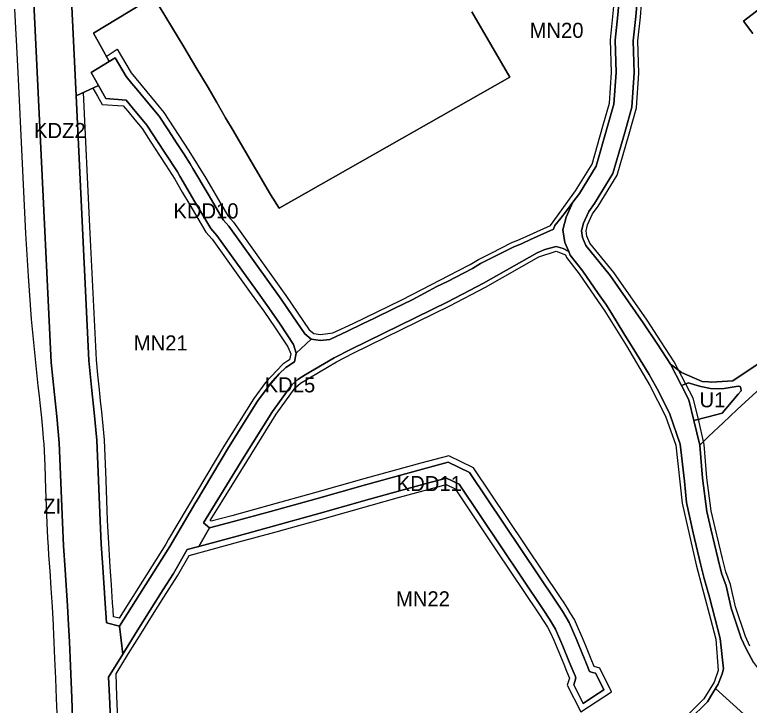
# Model space of a CAD drawing. Extents: x 7440055 to 7442242, y 5549003 to 5552256.
# Drawn here: x 7440527.7 to 7441014, y 5550680.3 to 5551137.8 of the extents above; entities that cross this region are included whole.
import ezdxf

# ---------------------------------------------------------------- set-up
doc = ezdxf.new("R2010")
doc.units = 0
for name, color, linetype in [('linie_rozgraniczajace', 7, 'Continuous'), ('linie_zabudowy_nieprzekraczalne', 7, 'Continuous'), ('oznaczenia_przeznaczen', 7, 'Continuous')]:
    doc.layers.add(name, color=color, linetype=linetype)

msp = doc.modelspace()

# ---------------------------------------------------------------- linework, layer by layer
at = {"layer": 'linie_rozgraniczajace'}
for points in [[(7440830.37, 5551139.67), (7440855.55, 5551096.35), (7440702.84, 5551009.63), (7440697, 5551018.73), (7440687.09, 5551035.67), (7440677.19, 5551052.65), (7440672.26, 5551061.09), (7440667.34, 5551069.53), (7440661.49, 5551079.54), (7440655.65, 5551089.56), (7440647.67, 5551103.05), (7440639.69, 5551116.53), (7440619.62, 5551149.85), (7440579.81, 5551125.56), (7440585.04, 5551116.14), (7440590.25, 5551106.84), (7440578.25, 5551099.45), (7440583.15, 5551090.81), (7440568.31, 5551084.03), (7440561.3, 5551229.74)], [(7440561.3, 5551229.74), (7440568.31, 5551084.03), (7440576.75, 5550908.58), (7440578.8, 5550888.77), (7440580.36, 5550874.18), (7440582.12, 5550855.83), (7440584.21, 5550802.55), (7440584.95, 5550787.34), (7440585.97, 5550771.61), (7440587.51, 5550747.86), (7440588.35, 5550734.83), (7440597.06, 5550732.72), (7440599.32, 5550714.25), (7440589.84, 5550698.98), (7440590.37, 5550686.14), (7440591.21, 5550666.06)], [(7440573.92, 5550172.69), (7440582.76, 5550197.27), (7440579.13, 5550273.35), (7440576.06, 5550392.67), (7440574.03, 5550461.9), (7440571.71, 5550531.98), (7440566.39, 5550642.67), (7440566.17, 5550647.16), (7440566.21, 5550665.57), (7440565.4, 5550685.1), (7440564.29, 5550711.77), (7440563.86, 5550722.35), (7440563.39, 5550733.5), (7440562.57, 5550746.25), (7440561.03, 5550769.99), (7440559.99, 5550785.92), (7440559.23, 5550801.45), (7440557.17, 5550854.15), (7440555.49, 5550871.65), (7440553.94, 5550886.18), (7440551.79, 5550907.38), (7440536.34, 5551228.21)], [(7440536.34, 5551228.21), (7440551.79, 5550907.38), (7440553.94, 5550886.18), (7440555.49, 5550871.65), (7440557.17, 5550854.15), (7440559.23, 5550801.45), (7440559.99, 5550785.92), (7440561.03, 5550769.99), (7440562.57, 5550746.25), (7440563.39, 5550733.5), (7440563.86, 5550722.35), (7440564.29, 5550711.77), (7440565.4, 5550685.1), (7440566.21, 5550665.57)], [(7440928.54, 5551156.26), (7440927.02, 5551137.61), (7440925.17, 5551120.94), (7440925.87, 5551099.38), (7440924.41, 5551078.59), (7440919.98, 5551063.06), (7440912.67, 5551037.44), (7440907.11, 5551028.4), (7440901.55, 5551019.35), (7440897.25, 5551013.55), (7440892.96, 5551007.75), (7440889.14, 5551002.96), (7440885.33, 5550998.16), (7440884.33, 5550995.64), (7440869.26, 5550988.88), (7440863.61, 5550986.23), (7440857.59, 5550983.83), (7440844.91, 5550977.34), (7440836.17, 5550972.94), (7440830.69, 5550969.6), (7440814.23, 5550961.11), (7440807.18, 5550957.61), (7440790.76, 5550948.96), (7440778.97, 5550943.15), (7440765.8, 5550936.74), (7440757.96, 5550932.92), (7440748, 5550928.18), (7440736.35, 5550922.68), (7440730.09, 5550921.98), (7440724.04, 5550922.85), (7440719.69, 5550926.27), (7440711.67, 5550938.27), (7440704, 5550949.42), (7440669.33, 5550997.74), (7440665.67, 5551001.91), (7440655.65, 5551018.94), (7440645.7, 5551035.85), (7440643.93, 5551038.87), (7440639.59, 5551045.54), (7440635.24, 5551052.2), (7440629.25, 5551061.39), (7440623.26, 5551070.58), (7440613.2, 5551082.79), (7440609.12, 5551087.6), (7440605.28, 5551092.25), (7440601.45, 5551096.91), (7440594.17, 5551109.25), (7440590.25, 5551106.84), (7440585.04, 5551116.14), (7440579.81, 5551125.56), (7440619.62, 5551149.85), (7440639.69, 5551116.53), (7440647.67, 5551103.05), (7440655.65, 5551089.56), (7440661.49, 5551079.54), (7440667.34, 5551069.53), (7440672.26, 5551061.09), (7440677.19, 5551052.65), (7440687.09, 5551035.67), (7440697, 5551018.73), (7440702.84, 5551009.63), (7440855.55, 5551096.35), (7440830.37, 5551139.67)], [(7441010.3, 5550674.43), (7440991.64, 5550691.44), (7440993.4, 5550694.37), (7440996.09, 5550701.19), (7440996.9, 5550704.49), (7440994.79, 5550724.62), (7440991.22, 5550738.27), (7440987.64, 5550751.91), (7440984.21, 5550764.34), (7440981.75, 5550773.95), (7440976.83, 5550794.47), (7440972.47, 5550814.57), (7440971.17, 5550828.79), (7440968.31, 5550853.23), (7440961.35, 5550873.06), (7440954.1, 5550887.88), (7440947.66, 5550899.42), (7440939.34, 5550913.21), (7440931.03, 5550926.58), (7440922.71, 5550939.96), (7440918.97, 5550945.95), (7440914.05, 5550953.02), (7440903.74, 5550967.82), (7440895.53, 5550978.55), (7440894.5, 5550980.96), (7440891.98, 5550986.84), (7440890.64, 5550995.24), (7440892.81, 5551003.56), (7440897.25, 5551013.55), (7440901.55, 5551019.35), (7440907.11, 5551028.4), (7440912.67, 5551037.44), (7440919.98, 5551063.06), (7440924.41, 5551078.59), (7440925.87, 5551099.38), (7440925.17, 5551120.94), (7440927.02, 5551137.61), (7440928.54, 5551156.26)], [(7440940.44, 5551154.55), (7440938.97, 5551136.46), (7440937.19, 5551120.47), (7440937.88, 5551099.15), (7440936.29, 5551076.5), (7440931.52, 5551059.77), (7440923.75, 5551032.57), (7440911.5, 5551012.62), (7440907.68, 5551007.46), (7440904.17, 5550999.58), (7440902.88, 5550994.65), (7440903.59, 5550990.2), (7440905.9, 5550984.81), (7440921.91, 5550965.1), (7440943.85, 5550933.7), (7440953.2, 5550919.47), (7440961.8, 5550906.31), (7440969.13, 5550892.18), (7440974.08, 5550882.66), (7440977.41, 5550869.05), (7440981.27, 5550852.56), (7440983.02, 5550830.68), (7440985.92, 5550808.58)], [(7440902.88, 5550994.65), (7440904.17, 5550999.58), (7440907.68, 5551007.46), (7440911.5, 5551012.62), (7440923.75, 5551032.57), (7440931.52, 5551059.77), (7440936.29, 5551076.5), (7440937.88, 5551099.15), (7440937.19, 5551120.47), (7440938.97, 5551136.46), (7440940.44, 5551154.55)], [(7441016.3, 5551125.31), (7441010.11, 5551133.47), (7441029.47, 5551148.49)], [(7441029.47, 5551148.49), (7441010.11, 5551133.47), (7441016.3, 5551125.31)], [(7440555.81, 5550675.03), (7440555.41, 5550684.69), (7440554.86, 5550698.02), (7440554.3, 5550711.36), (7440553.86, 5550721.94), (7440553.43, 5550732.51), (7440553.38, 5550733.43), (7440552.59, 5550745.61), (7440551.8, 5550757.78), (7440551.05, 5550769.34), (7440550.37, 5550779.81), (7440550.01, 5550785.35), (7440549.65, 5550790.89), (7440549.25, 5550801.01), (7440548.81, 5550812.22), (7440548.37, 5550823.42), (7440547.75, 5550839.07), (7440547.19, 5550853.48), (7440546.83, 5550857.06), (7440546.47, 5550860.64), (7440545.54, 5550870.64), (7440544.62, 5550880.64), (7440543.99, 5550885.14), (7440543.31, 5550891.84), (7440541.07, 5550913.93), (7440538.83, 5550936.02), (7440536.88, 5550964.45), (7440534.93, 5550992.87), (7440532.5, 5551043.93), (7440530.08, 5551094.99), (7440528.85, 5551120.92), (7440528.68, 5551124.58), (7440527.66, 5551141.39)], [(7441019.97, 5550906.59), (7441003.04, 5550895.28), (7440996.05, 5550894.8), (7440989.07, 5550894.32), (7440987.06, 5550894.5), (7440982.84, 5550894.87), (7440969.2, 5550900.82), (7440961.8, 5550906.31), (7440953.2, 5550919.47), (7440943.85, 5550933.7), (7440921.91, 5550965.1), (7440905.9, 5550984.81), (7440903.59, 5550990.2), (7440902.88, 5550994.65)], [(7440591.21, 5550666.06), (7440590.37, 5550686.14), (7440589.84, 5550698.98), (7440599.32, 5550714.25), (7440608.81, 5550729.52), (7440625.92, 5550757.04), (7440632.83, 5550767.67), (7440641.9, 5550783.4), (7440649.65, 5550785.5), (7440675.05, 5550792.36), (7440699.6, 5550799.09), (7440729.93, 5550807.47), (7440762.62, 5550816.79), (7440800.16, 5550827.16), (7440813.64, 5550830.69), (7440821.9, 5550826.7), (7440877.53, 5550743.73), (7440881.85, 5550737.27), (7440885.74, 5550730.65), (7440890.63, 5550719.56), (7440894.87, 5550709.12), (7440896.77, 5550704.44), (7440898.67, 5550699.76), (7440899.23, 5550698.4), (7440898.54, 5550696.11), (7440897.85, 5550693.83), (7440900.9, 5550687.7), (7440903.95, 5550681.57), (7440910.87, 5550686.02), (7440917.79, 5550690.46), (7440914.99, 5550696), (7440912.2, 5550701.53), (7440910.23, 5550702.11), (7440908.26, 5550702.7), (7440906.23, 5550707.71), (7440904.21, 5550712.71), (7440903.62, 5550714.16), (7440899.84, 5550723.46), (7440894.66, 5550735.22), (7440890.33, 5550742.58), (7440885.83, 5550749.3), (7440828.69, 5550834.53), (7440814.66, 5550841.29), (7440797.56, 5550836.81), (7440759.92, 5550826.42), (7440727.23, 5550817.1), (7440696.95, 5550808.73), (7440672.43, 5550802.01), (7440656.69, 5550797.76), (7440652.64, 5550801.17), (7440679.44, 5550844.71), (7440698.34, 5550874.88), (7440711.19, 5550892.59), (7440715.1, 5550896.18), (7440720.07, 5550899.24), (7440739.24, 5550910.39), (7440750.46, 5550916.27), (7440814.49, 5550947.54), (7440838.02, 5550959.86), (7440873.51, 5550980.06), (7440878.68, 5550982.11), (7440886.17, 5550984.24), (7440890.77, 5550982.84), (7440894.5, 5550980.96), (7440895.53, 5550978.55), (7440903.74, 5550967.82), (7440914.05, 5550953.02), (7440918.97, 5550945.95), (7440922.71, 5550939.96), (7440931.03, 5550926.58), (7440939.34, 5550913.21), (7440947.66, 5550899.42), (7440954.1, 5550887.88), (7440961.35, 5550873.06), (7440968.31, 5550853.23), (7440971.17, 5550828.79), (7440972.47, 5550814.57), (7440976.83, 5550794.47), (7440981.75, 5550773.95), (7440984.21, 5550764.34), (7440987.64, 5550751.91), (7440991.22, 5550738.27), (7440994.79, 5550724.62), (7440996.9, 5550704.49), (7440996.09, 5550701.19), (7440993.4, 5550694.37), (7440991.64, 5550691.44), (7440989.88, 5550688.5), (7440986.37, 5550682.63), (7440974.26, 5550670.64)], [(7441021.65, 5550890.55), (7441006.03, 5550876.25), (7440996.62, 5550867.42), (7440987.21, 5550858.58), (7440981.27, 5550852.56), (7440977.41, 5550869.05), (7440986.76, 5550871.41), (7440996.12, 5550873.77), (7441006.72, 5550886.42), (7441008.56, 5550888.6), (7441008.46, 5550890.36), (7441007.92, 5550891.37), (7441006.86, 5550891.79), (7441005.24, 5550891.51), (7440997.43, 5550890.16), (7440993.69, 5550889.97), (7440988.24, 5550890.24), (7440981.89, 5550891.42), (7440977.88, 5550892.66), (7440973.88, 5550893.9), (7440969.13, 5550892.18), (7440961.8, 5550906.31), (7440969.2, 5550900.82), (7440982.84, 5550894.87), (7440987.06, 5550894.5), (7440989.07, 5550894.32), (7440996.05, 5550894.8), (7441003.04, 5550895.28), (7441019.97, 5550906.59)], [(7441016.81, 5550708.73), (7441011.75, 5550718.07), (7441008.62, 5550724.81), (7441002.01, 5550744.64), (7440998.67, 5550759.48), (7440995.7, 5550767.84), (7440993.4, 5550776.83), (7440988.51, 5550797.2), (7440985.92, 5550808.58), (7440983.02, 5550830.68), (7440981.27, 5550852.56), (7440987.21, 5550858.58), (7440996.62, 5550867.42), (7441006.03, 5550876.25), (7441021.65, 5550890.55)], [(7440985.92, 5550808.58), (7440988.51, 5550797.2), (7440993.4, 5550776.83), (7440995.7, 5550767.84), (7440998.67, 5550759.48), (7441002.01, 5550744.64), (7441008.62, 5550724.81), (7441011.75, 5550718.07), (7441016.81, 5550708.73), (7441021.5, 5550702.43), (7441027.75, 5550694.5), (7441043.14, 5550686.11), (7441057.84, 5550678.1)], [(7440974.26, 5550670.64), (7440986.37, 5550682.63), (7440989.88, 5550688.5), (7440991.64, 5550691.44), (7441010.3, 5550674.43)]]:
    msp.add_lwpolyline(points, dxfattribs=at)
for points in [[(7440578.25, 5551099.45), (7440590.25, 5551106.84), (7440594.17, 5551109.25), (7440601.45, 5551096.91), (7440605.28, 5551092.25), (7440609.12, 5551087.6), (7440613.2, 5551082.79), (7440623.26, 5551070.58), (7440629.25, 5551061.39), (7440635.24, 5551052.2), (7440639.59, 5551045.54), (7440643.93, 5551038.87), (7440645.7, 5551035.85), (7440655.65, 5551018.94), (7440665.67, 5551001.91), (7440669.33, 5550997.74), (7440704, 5550949.42), (7440711.67, 5550938.27), (7440719.69, 5550926.27), (7440724.04, 5550922.85), (7440714.02, 5550913.56), (7440712.26, 5550919.39), (7440703.4, 5550932.66), (7440695.82, 5550943.66), (7440687.68, 5550955.01), (7440661.49, 5550991.51), (7440657.53, 5550996.03), (7440647.03, 5551013.87), (7440637.08, 5551030.78), (7440635.43, 5551033.6), (7440626.87, 5551046.75), (7440615.19, 5551064.65), (7440605.53, 5551076.38), (7440601.45, 5551081.19), (7440588.04, 5551082.17), (7440583.15, 5551090.81)], [(7440568.31, 5551084.03), (7440583.15, 5551090.81), (7440588.04, 5551082.17), (7440601.45, 5551081.19), (7440605.53, 5551076.38), (7440615.19, 5551064.65), (7440626.87, 5551046.75), (7440635.43, 5551033.6), (7440637.08, 5551030.78), (7440647.03, 5551013.87), (7440657.53, 5550996.03), (7440661.49, 5550991.51), (7440687.68, 5550955.01), (7440695.82, 5550943.66), (7440703.4, 5550932.66), (7440712.26, 5550919.39), (7440714.02, 5550913.56), (7440712.89, 5550907.73), (7440707.21, 5550903.97), (7440702.84, 5550899.83), (7440696.08, 5550892.16), (7440688.48, 5550881.74), (7440669.2, 5550850.98), (7440647.73, 5550814.97), (7440647.62, 5550814.78), (7440630.35, 5550785.37), (7440597.06, 5550732.72), (7440588.35, 5550734.83), (7440587.51, 5550747.86), (7440585.97, 5550771.61), (7440584.95, 5550787.34), (7440584.21, 5550802.55), (7440582.12, 5550855.83), (7440580.36, 5550874.18), (7440578.8, 5550888.77), (7440576.75, 5550908.58)], [(7440597.06, 5550732.72), (7440630.35, 5550785.37), (7440647.62, 5550814.78), (7440647.73, 5550814.97), (7440669.2, 5550850.98), (7440688.48, 5550881.74), (7440696.08, 5550892.16), (7440702.84, 5550899.83), (7440707.21, 5550903.97), (7440712.89, 5550907.73), (7440714.02, 5550913.56), (7440724.04, 5550922.85), (7440730.09, 5550921.98), (7440736.35, 5550922.68), (7440748, 5550928.18), (7440757.96, 5550932.92), (7440765.8, 5550936.74), (7440778.97, 5550943.15), (7440790.76, 5550948.96), (7440807.18, 5550957.61), (7440814.23, 5550961.11), (7440830.69, 5550969.6), (7440836.17, 5550972.94), (7440844.91, 5550977.34), (7440857.59, 5550983.83), (7440863.61, 5550986.23), (7440869.26, 5550988.88), (7440884.33, 5550995.64), (7440885.33, 5550998.16), (7440889.14, 5551002.96), (7440892.96, 5551007.75), (7440897.25, 5551013.55), (7440892.81, 5551003.56), (7440890.64, 5550995.24), (7440891.98, 5550986.84), (7440894.5, 5550980.96), (7440890.77, 5550982.84), (7440886.17, 5550984.24), (7440878.68, 5550982.11), (7440873.51, 5550980.06), (7440838.02, 5550959.86), (7440814.49, 5550947.54), (7440750.46, 5550916.27), (7440739.24, 5550910.39), (7440720.07, 5550899.24), (7440715.1, 5550896.18), (7440711.19, 5550892.59), (7440698.34, 5550874.88), (7440679.44, 5550844.71), (7440652.64, 5550801.17), (7440656.69, 5550797.76), (7440649.65, 5550785.5), (7440641.9, 5550783.4), (7440632.83, 5550767.67), (7440625.92, 5550757.04), (7440608.81, 5550729.52), (7440599.32, 5550714.25)], [(7440969.13, 5550892.18), (7440973.88, 5550893.9), (7440977.88, 5550892.66), (7440981.89, 5550891.42), (7440988.24, 5550890.24), (7440993.69, 5550889.97), (7440997.43, 5550890.16), (7441005.24, 5550891.51), (7441006.86, 5550891.79), (7441007.92, 5550891.37), (7441008.46, 5550890.36), (7441008.56, 5550888.6), (7441006.72, 5550886.42), (7440996.12, 5550873.77), (7440986.76, 5550871.41), (7440977.41, 5550869.05), (7440974.08, 5550882.66)], [(7440649.65, 5550785.5), (7440656.69, 5550797.76), (7440672.43, 5550802.01), (7440696.95, 5550808.73), (7440727.23, 5550817.1), (7440759.92, 5550826.42), (7440797.56, 5550836.81), (7440814.66, 5550841.29), (7440828.69, 5550834.53), (7440885.83, 5550749.3), (7440890.33, 5550742.58), (7440894.66, 5550735.22), (7440899.84, 5550723.46), (7440903.62, 5550714.16), (7440904.21, 5550712.71), (7440906.23, 5550707.71), (7440908.26, 5550702.7), (7440910.23, 5550702.11), (7440912.2, 5550701.53), (7440914.99, 5550696), (7440917.79, 5550690.46), (7440910.87, 5550686.02), (7440903.95, 5550681.57), (7440900.9, 5550687.7), (7440897.85, 5550693.83), (7440898.54, 5550696.11), (7440899.23, 5550698.4), (7440898.67, 5550699.76), (7440896.77, 5550704.44), (7440894.87, 5550709.12), (7440890.63, 5550719.56), (7440885.74, 5550730.65), (7440881.85, 5550737.27), (7440877.53, 5550743.73), (7440821.9, 5550826.7), (7440813.64, 5550830.69), (7440800.16, 5550827.16), (7440762.62, 5550816.79), (7440729.93, 5550807.47), (7440699.6, 5550799.09), (7440675.05, 5550792.36)]]:
    msp.add_lwpolyline(points, close=True, dxfattribs=at)
at = {"layer": 'linie_zabudowy_nieprzekraczalne'}
for points in [[(7440588.12, 5551110.08), (7440595.5, 5551114.89), (7440604.73, 5551099.21), (7440621.31, 5551079.24), (7440626.49, 5551072.95), (7440642.97, 5551047.67), (7440654.11, 5551029.45), (7440664.1, 5551012.45), (7440668.92, 5551004.26), (7440672.46, 5551000.23), (7440707.28, 5550951.71), (7440722.65, 5550929.03), (7440725.67, 5550926.66), (7440730.16, 5550926.02), (7440738.3, 5550926.92), (7440751.69, 5550933.25), (7440783.52, 5550948.74), (7440797.6, 5550955.96), (7440821.09, 5550968.02), (7440829.22, 5550972.22), (7440834.71, 5550975.56), (7440843.55, 5550980.02), (7440856.35, 5550986.57), (7440862.43, 5550988.99), (7440882.36, 5550998.04), (7440892.68, 5551012.42), (7440899.06, 5551021.03), (7440909.9, 5551038.66), (7440917.09, 5551063.89), (7440921.44, 5551079.11), (7440922.87, 5551099.43), (7440922.16, 5551121.03), (7440925.57, 5551156.73)], [(7441014.43, 5550719.42), (7441011.42, 5550725.92), (7441004.9, 5550745.44), (7441001.56, 5550760.32), (7440998.57, 5550768.72), (7440996.31, 5550777.55), (7440991.43, 5550797.89), (7440988.88, 5550809.11), (7440986.01, 5550831), (7440984.25, 5550853.03), (7440980.33, 5550869.75), (7440976.91, 5550883.72), (7440964.39, 5550907.82), (7440955.7, 5550921.11), (7440946.34, 5550935.38), (7440924.3, 5550966.91), (7440908.49, 5550986.38), (7440906.5, 5550991.04), (7440905.94, 5550994.5), (7440907.01, 5550998.59), (7440910.28, 5551005.94), (7440913.99, 5551010.94), (7440926.52, 5551031.35), (7440934.4, 5551058.95), (7440939.26, 5551075.98), (7440940.88, 5551099.09), (7440940.19, 5551120.35), (7440941.95, 5551136.17), (7440943.41, 5551154.12)], [(7440579.49, 5551089.14), (7440582.56, 5551083.74), (7440585.62, 5551078.33), (7440599.48, 5551077.32), (7440602.46, 5551073.81), (7440607.21, 5551068.05), (7440611.96, 5551062.28), (7440617.74, 5551053.42), (7440623.52, 5551044.56), (7440627.77, 5551038.03), (7440633.64, 5551028.75), (7440638.61, 5551020.3), (7440643.58, 5551011.84), (7440648.93, 5551002.76), (7440654.27, 5550993.67), (7440658.35, 5550989.02), (7440675.45, 5550965.19), (7440684.25, 5550952.92), (7440692.54, 5550941.36), (7440700.09, 5550930.42), (7440708.61, 5550917.66), (7440710.5, 5550913.04), (7440709.59, 5550909.12), (7440708.41, 5550908.36), (7440705.27, 5550906.28), (7440693.76, 5550894.08), (7440685.99, 5550883.42), (7440666.64, 5550852.54), (7440629.56, 5550790.36), (7440627.78, 5550786.93), (7440612.29, 5550762.43), (7440596.8, 5550737.92), (7440593.11, 5550738.82), (7440592.8, 5550743.5), (7440592.5, 5550748.18), (7440591.73, 5550760.06), (7440590.96, 5550771.94), (7440590.45, 5550779.78), (7440589.94, 5550787.62), (7440589.2, 5550802.77), (7440588.16, 5550829.47), (7440587.11, 5550856.17), (7440586.22, 5550865.42), (7440585.34, 5550874.68), (7440584.55, 5550881.99), (7440583.77, 5550889.29), (7440582.75, 5550899.2), (7440581.73, 5550909.1), (7440577.48, 5550997.55), (7440573.21, 5551086.27)], [(7440596.21, 5550666.16), (7440595.37, 5550686.34), (7440594.75, 5550701.2), (7440603.05, 5550714.57), (7440611.35, 5550727.93), (7440618.91, 5550739.94), (7440626.46, 5550751.95), (7440635.4, 5550766.12), (7440643.18, 5550779.6), (7440676.11, 5550788.5), (7440688.39, 5550791.87), (7440700.67, 5550795.24), (7440715.84, 5550799.43), (7440731.01, 5550803.62), (7440747.36, 5550808.28), (7440763.7, 5550812.94), (7440782.45, 5550818.12), (7440807.92, 5550825.06), (7440813.23, 5550826.46), (7440819.19, 5550823.57), (7440846.69, 5550782.54), (7440874.2, 5550741.5), (7440878.47, 5550735.14), (7440880.32, 5550731.98), (7440882.17, 5550728.83), (7440884.56, 5550723.41), (7440889.06, 5550712.81), (7440891.17, 5550707.62), (7440893.08, 5550702.91), (7440894.99, 5550698.2), (7440893.47, 5550693.61), (7440902.49, 5550675.88), (7440922.9, 5550689.1), (7440915.1, 5550704.91), (7440911.37, 5550705.95), (7440909.35, 5550710.8), (7440906.15, 5550718.56), (7440903.53, 5550725.02), (7440900.87, 5550731.03), (7440898.22, 5550737.05), (7440895.97, 5550740.88), (7440893.72, 5550744.71), (7440891.44, 5550748.12), (7440889.1, 5550751.72), (7440831.41, 5550837.66), (7440815.07, 5550845.53), (7440796.52, 5550840.68), (7440758.83, 5550830.27), (7440726.15, 5550820.95), (7440695.89, 5550812.59), (7440671.38, 5550805.87), (7440657.66, 5550802.16), (7440657.08, 5550802.66), (7440664.74, 5550815.11), (7440700.83, 5550873.21), (7440713.44, 5550890.59), (7440716.89, 5550893.76), (7440740.7, 5550907.77), (7440751.81, 5550913.59), (7440815.84, 5550944.86), (7440839.46, 5550957.23), (7440874.74, 5550977.31), (7440886.08, 5550981.05), (7440892.23, 5550978.63), (7440892.92, 5550977.02), (7440901.32, 5550966.05), (7440911.57, 5550951.33), (7440918.32, 5550941.32), (7440932.62, 5550918.34), (7440948.26, 5550892.2), (7440958.58, 5550871.88), (7440965.36, 5550852.57), (7440969.5, 5550814.08), (7440978.84, 5550773.23), (7440983.03, 5550757.35), (7440988.32, 5550737.5), (7440991.82, 5550724.12), (7440993.46, 5550703.26), (7440990.68, 5550695.67), (7440983.99, 5550684.49), (7440960.16, 5550660.9)]]:
    msp.add_lwpolyline(points, dxfattribs=at)

# ---------------------------------------------------------------- texts
at = {"layer": 'oznaczenia_przeznaczen'}
for s, p in [('MN20', (7440868.6, 5551122.4)), ('KDZ2', (7440540.45, 5551056.01)), ('KDD10', (7440632.75, 5551002.81)), ('MN21', (7440606.53, 5550915.33)), ('KDL5', (7440693.16, 5550887.59)), ('U1', (7440981.08, 5550877.68)), ('KDD11', (7440780.6, 5550822.16)), ('ZI', (7440546.54, 5550807.22)), ('MN22', (7440780.13, 5550745.78))]:
    msp.add_text(s, height=10, dxfattribs=at).set_placement(p)

doc.saveas('drawing.dxf')
